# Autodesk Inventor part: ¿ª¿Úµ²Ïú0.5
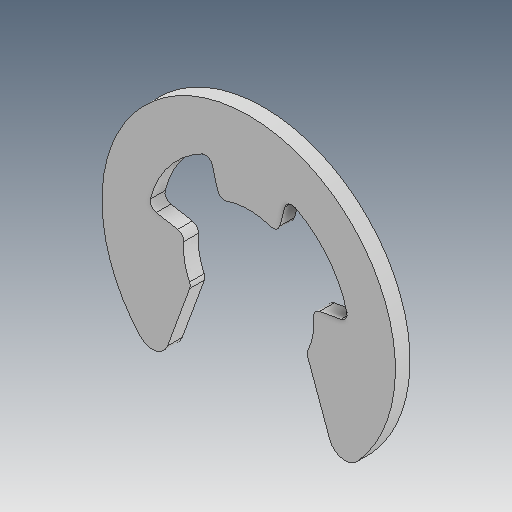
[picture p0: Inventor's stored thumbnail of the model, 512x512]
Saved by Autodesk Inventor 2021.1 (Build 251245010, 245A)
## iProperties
Created: 2015-08
Part Number: ¿ª¿Úµ²Ïú0.5
Material: Ogólny
Document SubType Name: Modeling
Designer: user
Density: 1 g/cm^3
Appearance: Domyślna
Author: user
Revision Number: ÈÎºÎ
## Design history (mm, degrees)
feature "Í¹Ì¨-À­Éì1"
node "Bryła1"
